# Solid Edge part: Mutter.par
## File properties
Sűrűség: 0,000 kg/m^3
Pontosság: 0,990
Author: ahadarics
Last saved by: psaghy
Revision: 77
Username: ahadarics
Dokumentum tartalom típus: 0
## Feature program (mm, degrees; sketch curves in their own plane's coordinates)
base feature "unnamed BaseFeature 1"
sketch for "Furat_1" plane through (8, 0, 0) normal (1, 0, 0) x-axis (0, 1, 0)
hole "Furat_1" through  StartChamferOffset = 0.47 mm; StartChamferAngle = 45 deg
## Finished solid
Body 1: solid body, 23 faces, 47 edges, 26 vertices.
  Faces by surface: cone 14, plane 8, cylinder 1
  Edges by curve: spline 24, circle 16, line 7
Bounding box of the edges (mm): 8.000 x 27.713 x 24.000, from (0, -13.8564, -12) to (8, 13.8564, 12).
Cylindrical faces by radius (mm): R7.188 x1
Conical faces (half-angle, radius in mm at the cone's reference point): 45 deg R7.658 x1, 60 deg R7.5939 x1, 60 deg R12.9282 x12
Planar faces by outward normal: +x 1, +z 1, -x 1, -z 1, oblique 4
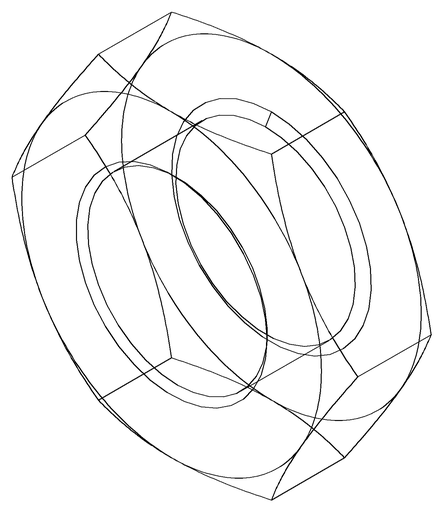
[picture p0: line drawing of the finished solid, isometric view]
